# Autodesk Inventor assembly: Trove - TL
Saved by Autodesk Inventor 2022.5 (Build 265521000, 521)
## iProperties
Created: 2024-07
Part Number: Trove - TL
Document SubType Name: Assembly
Designer: AdminForWorker
Title: Trove - TL v7
Author: AdminForWorker
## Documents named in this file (2)
- z:\worker\convert-fusion-r03-cosv3\tmp\job-1\64\temp\files\890c6e9e-8bc5-494b-9aa5-545fa39bf4ab\Trove - TL v7.iam
- z:\worker\convert-fusion-r03-cosv3\tmp\job-1\64\temp\files\890c6e9e-8bc5-494b-9aa5-545fa39bf4ab\Trove - TL.ipt
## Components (1 placed, 1 different names)
1. Trove - TL:1
